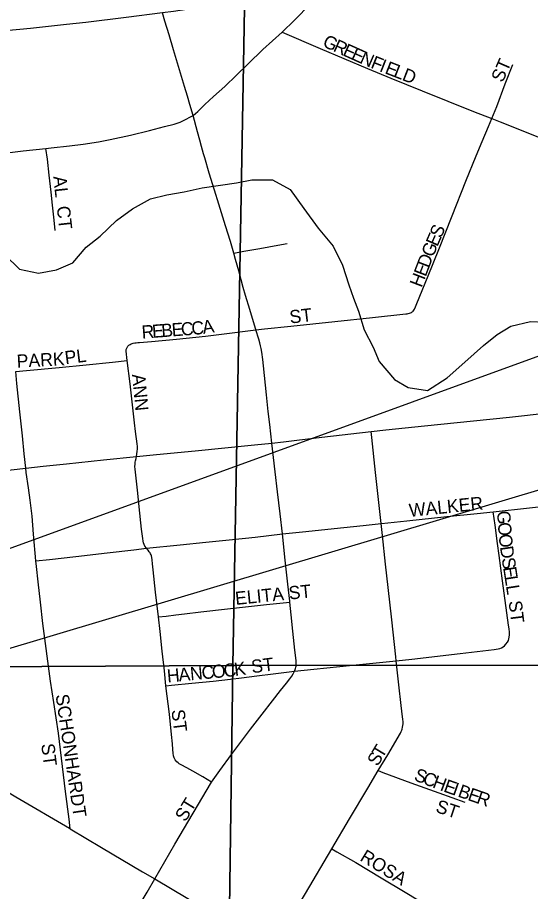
# Model space of a CAD drawing. Extents: x 0 to 34, y 0 to 22.
# Drawn here: x 5.9131 to 6.0976, y 18.3375 to 18.6521 of the extents above; entities that cross this region are included whole.
import ezdxf

# ---------------------------------------------------------------- set-up
doc = ezdxf.new("R2010")
doc.units = 0
for name, color, linetype in [('GM_X_City_Street', 7, 'Continuous'), ('GM_X_City_Street_Text', 7, 'Continuous'), ('GM_X_Minor_River', 7, 'Continuous'), ('GM_X_Section', 7, 'Continuous'), ('GM_X_State_Route', 7, 'Continuous'), ('SH_Text', 7, 'Continuous')]:
    doc.layers.add(name, color=color, linetype=linetype)

msp = doc.modelspace()

# ---------------------------------------------------------------- linework, layer by layer
at = {"layer": 'GM_X_City_Street'}
for points in [[(5.97623, 18.6169), (5.9751, 18.62082), (5.97423, 18.62383), (5.97321, 18.62735), (5.97211, 18.6309), (5.96925, 18.64045), (5.96763, 18.64587), (5.96614, 18.65085), (5.96526, 18.65378)], [(6.00829, 18.64679), (6.02199, 18.64096), (6.03895, 18.63373), (6.04742, 18.63029), (6.05863, 18.62578), (6.07711, 18.61832), (6.08371, 18.61573)], [(6.08371, 18.61573), (6.08545, 18.62011), (6.08855, 18.62823), (6.09128, 18.63517)], [(5.99093, 18.56728), (5.9897, 18.57147), (5.98794, 18.57712), (5.9855, 18.58494), (5.98398, 18.58994), (5.98207, 18.59612), (5.98044, 18.60161), (5.98002, 18.60302), (5.97931, 18.60566), (5.97867, 18.60798), (5.97785, 18.61094), (5.97623, 18.6169)], [(6.05443, 18.54579), (6.05479, 18.54599), (6.05506, 18.54618), (6.05523, 18.54633), (6.05538, 18.54648), (6.05565, 18.54682), (6.05583, 18.54713), (6.05598, 18.5474), (6.05676, 18.54914), (6.06078, 18.55918), (6.06462, 18.56867), (6.06944, 18.58076), (6.07437, 18.59316), (6.07811, 18.60236), (6.08025, 18.60752), (6.08249, 18.61284), (6.08371, 18.61573)], [(6.08371, 18.61573), (6.08668, 18.61457), (6.11581, 18.60294), (6.16051, 18.58493), (6.1907, 18.57271), (6.19139, 18.57243)], [(5.9267, 18.57545), (5.92632, 18.57923), (5.92572, 18.58463), (5.9252, 18.58929), (5.92452, 18.59537), (5.92387, 18.60115), (5.92335, 18.60502)], [(5.99093, 18.56728), (5.99457, 18.568), (6.00022, 18.56903), (6.00679, 18.57022), (6.01014, 18.57081)], [(5.99887, 18.53976), (5.99886, 18.5398), (5.99765, 18.54378), (5.99668, 18.54701), (5.99514, 18.55204), (5.99428, 18.555), (5.99267, 18.56099), (5.99157, 18.56507), (5.99093, 18.56728)], [(5.99887, 18.53976), (6.00193, 18.54012), (6.01144, 18.54108), (6.02726, 18.54266), (6.04076, 18.54413), (6.05279, 18.54541), (6.05326, 18.54546), (6.05366, 18.54553), (6.05409, 18.54566), (6.05443, 18.54579)], [(5.95284, 18.53383), (5.9532, 18.53418), (5.95363, 18.53444), (5.95403, 18.53465), (5.95439, 18.5348), (5.95474, 18.53491), (5.95527, 18.535), (5.95581, 18.53507), (5.9564, 18.53511), (5.95699, 18.53516), (5.96129, 18.53554), (5.97024, 18.53635), (5.98068, 18.5374), (5.98745, 18.53828), (5.99887, 18.53976)], [(6.00454, 18.49886), (6.00382, 18.50566), (6.0033, 18.51037), (6.0027, 18.51631), (6.00162, 18.5267), (6.0013, 18.52904), (6.00096, 18.53164), (6.00072, 18.53303), (6.00054, 18.534), (6.0003, 18.53498), (5.99992, 18.53633), (5.99887, 18.53976)], [(5.9526, 18.52869), (5.95217, 18.532), (5.95222, 18.53257), (5.95239, 18.53313), (5.95262, 18.53353), (5.95284, 18.53383)], [(5.91248, 18.52474), (5.91641, 18.52503), (5.92809, 18.52613), (5.93786, 18.52711), (5.94725, 18.52812), (5.9526, 18.52869)], [(5.95591, 18.49413), (5.95619, 18.49589), (5.95626, 18.49683), (5.95622, 18.4977), (5.95616, 18.49864), (5.95561, 18.50308), (5.95525, 18.50629), (5.95477, 18.51058), (5.95361, 18.52025), (5.9526, 18.52869)], [(5.91606, 18.48991), (5.91553, 18.49504), (5.91486, 18.50159), (5.91398, 18.51015), (5.91292, 18.52041), (5.91248, 18.52474)], [(6.04029, 18.50307), (6.04562, 18.50366), (6.05953, 18.5051), (6.07708, 18.50692), (6.09009, 18.50832), (6.11788, 18.51135), (6.13438, 18.51308), (6.14881, 18.51459), (6.15926, 18.51574), (6.16919, 18.51683), (6.19705, 18.51978)], [(6.00454, 18.49886), (6.00879, 18.49941), (6.0136, 18.50005), (6.02256, 18.5011), (6.04029, 18.50307)], [(6.04388, 18.46995), (6.04319, 18.47645), (6.04187, 18.48837), (6.04051, 18.50099), (6.04029, 18.50307)], [(5.95591, 18.49413), (5.96307, 18.49483), (5.97696, 18.49618), (5.99836, 18.49826), (6.00454, 18.49886)], [(6.00836, 18.46627), (6.00753, 18.47343), (6.00661, 18.48136), (6.00578, 18.48855), (6.00454, 18.49886)], [(5.91606, 18.48991), (5.92231, 18.49059), (5.93075, 18.4915), (5.94401, 18.49288), (5.95591, 18.49413)], [(5.95954, 18.4611), (5.95895, 18.46187), (5.95864, 18.46241), (5.95841, 18.46302), (5.95828, 18.46366), (5.95814, 18.46457), (5.95776, 18.46797), (5.95689, 18.47603), (5.95639, 18.48088), (5.95544, 18.48952), (5.95536, 18.49047), (5.95539, 18.49136), (5.95547, 18.49205), (5.95555, 18.4926), (5.95575, 18.49344), (5.95591, 18.49413)], [(5.87222, 18.48524), (5.87988, 18.48607), (5.89608, 18.48771), (5.90517, 18.48872), (5.91081, 18.48934), (5.91606, 18.48991)], [(5.91971, 18.45651), (5.91891, 18.46616), (5.91833, 18.47268), (5.91772, 18.47838), (5.91709, 18.48279), (5.91627, 18.48837), (5.91606, 18.48991)], [(6.08422, 18.47426), (6.0972, 18.47562), (6.10914, 18.47691), (6.12269, 18.47829), (6.1322, 18.47915), (6.13746, 18.47967)], [(6.04388, 18.46995), (6.04398, 18.46996), (6.05312, 18.47094), (6.06753, 18.47248), (6.07843, 18.47364), (6.08422, 18.47426)], [(6.08872, 18.42652), (6.08933, 18.42729), (6.08966, 18.4279), (6.08987, 18.42848), (6.08997, 18.42909), (6.09004, 18.42993), (6.09002, 18.43085), (6.08989, 18.43207), (6.08972, 18.4334), (6.08759, 18.44937), (6.0863, 18.45846), (6.08569, 18.46276), (6.08484, 18.46943), (6.08422, 18.47426)], [(6.00836, 18.46627), (6.01561, 18.46702), (6.03048, 18.46856), (6.03747, 18.46928), (6.04388, 18.46995)], [(6.04927, 18.42062), (6.04912, 18.42196), (6.04772, 18.43533), (6.0464, 18.44696), (6.0455, 18.45531), (6.04434, 18.46567), (6.04388, 18.46995)], [(5.95954, 18.4611), (5.97157, 18.46234), (5.9808, 18.46328), (5.99045, 18.46426), (5.99863, 18.46509), (6.00836, 18.46627)], [(6.01104, 18.44167), (6.011, 18.44205), (6.01034, 18.44819), (6.0094, 18.45685), (6.00836, 18.46627)], [(5.91971, 18.45651), (5.92467, 18.45708), (5.93409, 18.45816), (5.94541, 18.45947), (5.9549, 18.46057), (5.95954, 18.4611)], [(5.96386, 18.43637), (5.96323, 18.44132), (5.96272, 18.44531), (5.96188, 18.45338), (5.96166, 18.45547), (5.96152, 18.45694), (5.96141, 18.45772), (5.96127, 18.45835), (5.96113, 18.45875), (5.96098, 18.4591), (5.96079, 18.45942), (5.96052, 18.45982), (5.96008, 18.46041), (5.95954, 18.4611)], [(5.93206, 18.36014), (5.93164, 18.36357), (5.93043, 18.3735), (5.92786, 18.39454), (5.92616, 18.40553), (5.925, 18.41328), (5.92228, 18.43404), (5.92138, 18.44168), (5.92052, 18.44903), (5.91993, 18.45449), (5.91971, 18.45651)], [(5.96386, 18.43637), (5.96662, 18.4367), (5.97005, 18.43712), (5.97315, 18.4375), (5.97903, 18.43819), (5.98863, 18.43927), (5.99408, 18.43988), (6.00264, 18.44087), (6.01104, 18.44167)], [(6.01274, 18.4169), (6.01296, 18.41745), (6.01311, 18.41787), (6.01324, 18.41829), (6.0133, 18.4187), (6.01335, 18.41912), (6.01337, 18.41963), (6.01333, 18.4201), (6.01328, 18.42071), (6.01289, 18.4244), (6.01209, 18.4312), (6.01153, 18.4371), (6.01104, 18.44167)], [(5.9665, 18.41162), (5.96593, 18.41693), (5.96509, 18.42404), (5.96439, 18.43114), (5.96386, 18.43637)], [(6.04927, 18.42062), (6.05498, 18.4212), (6.07226, 18.42323), (6.08454, 18.42471), (6.08596, 18.4249), (6.08659, 18.42507), (6.0872, 18.42531), (6.08773, 18.42562), (6.08825, 18.42602), (6.08872, 18.42652)], [(6.01274, 18.4169), (6.01968, 18.41763), (6.03371, 18.41905), (6.04927, 18.42062)], [(6.04287, 18.38105), (6.04632, 18.38674), (6.05084, 18.39456), (6.05111, 18.39515), (6.0513, 18.39556), (6.05146, 18.39602), (6.05163, 18.39665), (6.05174, 18.39731), (6.05177, 18.39791), (6.05178, 18.39867), (6.05169, 18.39958), (6.05161, 18.4004), (6.05108, 18.40447), (6.05026, 18.41195), (6.04927, 18.42062)], [(5.9665, 18.41162), (5.96853, 18.41181), (5.97583, 18.41249), (5.9835, 18.41331), (5.98967, 18.41398), (5.99366, 18.41446), (5.99643, 18.41482), (5.9992, 18.41517), (6.00504, 18.41587), (6.01269, 18.4169), (6.01274, 18.4169)], [(5.98292, 18.37693), (5.98582, 18.38106), (5.99008, 18.38682), (5.99694, 18.39598), (6.00111, 18.40132), (6.00484, 18.40617), (6.00775, 18.40991), (6.00991, 18.41258), (6.0111, 18.41413), (6.0118, 18.4151), (6.01223, 18.41586), (6.01253, 18.41635), (6.01274, 18.4169)], [(5.98292, 18.37693), (5.97971, 18.37881), (5.97613, 18.38082), (5.97396, 18.38203), (5.97199, 18.38313), (5.97125, 18.38355), (5.97084, 18.38383), (5.97041, 18.38423), (5.96983, 18.38493), (5.96947, 18.38566), (5.96925, 18.38641), (5.96913, 18.38739), (5.96903, 18.38861), (5.96884, 18.39066), (5.96854, 18.39405), (5.96778, 18.40136), (5.9665, 18.41162)], [(5.88289, 18.3892), (5.89492, 18.38214), (5.91256, 18.37166), (5.93177, 18.36031), (5.93206, 18.36014)], [(6.0261, 18.35291), (6.03246, 18.36375), (6.03906, 18.37475), (6.04287, 18.38105)], [(6.04287, 18.38105), (6.04455, 18.38042), (6.05454, 18.37668), (6.06466, 18.37302), (6.07399, 18.36969)], [(5.96247, 18.34205), (5.96971, 18.35458), (5.98292, 18.37693)], [(5.93206, 18.36014), (5.94337, 18.35341), (5.95804, 18.34466), (5.96247, 18.34205)], [(6.00491, 18.31708), (6.0067, 18.32012), (6.01183, 18.32859), (6.01666, 18.33686), (6.0261, 18.35291)], [(6.0261, 18.35291), (6.02799, 18.35183), (6.03473, 18.34796), (6.04394, 18.34247), (6.05254, 18.33728), (6.06168, 18.33184)], [(5.92844, 18.30025), (5.93343, 18.30396), (5.93716, 18.30674), (5.9435, 18.31176), (5.94429, 18.31246), (5.94502, 18.31325), (5.94559, 18.31399), (5.94634, 18.31505), (5.94696, 18.31599), (5.95193, 18.32428), (5.9597, 18.33726), (5.96247, 18.34205)], [(5.96247, 18.34205), (5.97435, 18.33504), (5.98831, 18.32678), (6.00491, 18.31708)]]:
    msp.add_lwpolyline(points, dxfattribs=at)
at = {"layer": 'GM_X_Minor_River'}
msp.add_lwpolyline([(5.90861, 18.5667), (5.91388, 18.56154), (5.9207, 18.56016), (5.92716, 18.56125), (5.93306, 18.56386), (5.93785, 18.56952), (5.94281, 18.57346), (5.94873, 18.57911), (5.95445, 18.58324), (5.96093, 18.5868), (5.96682, 18.58827), (5.97309, 18.58936), (5.97955, 18.59083), (5.9919, 18.59264), (5.99741, 18.59373), (6.00481, 18.59368), (6.01123, 18.59021), (6.01612, 18.58335), (6.02119, 18.57629), (6.02664, 18.56979), (6.03001, 18.56294), (6.03223, 18.5559), (6.03391, 18.55115), (6.03577, 18.54639), (6.03781, 18.53973), (6.04099, 18.53344), (6.04323, 18.52831), (6.04868, 18.52181), (6.0536, 18.51893), (6.06061, 18.51793), (6.06766, 18.52243), (6.07396, 18.52807), (6.08065, 18.5341), (6.08561, 18.53804), (6.09057, 18.54104), (6.0976, 18.54269), (6.10272, 18.54247)], dxfattribs=at)
at = {"layer": 'GM_X_Section'}
msp.add_lwpolyline([(5.751, 18.66593), (5.77962, 18.69224), (5.79353, 18.70237), (5.81311, 18.71094), (5.83598, 18.72819), (5.85394, 18.74739), (5.86623, 18.76965), (5.88363, 18.79055), (5.90361, 18.82773), (5.91254, 18.85494), (5.91525, 18.86288), (5.91821, 18.87821), (5.92198, 18.90091), (5.93271, 18.91713), (5.93348, 18.91883), (5.93772, 18.9277), (5.9505, 18.93954), (5.96741, 18.95343), (5.99942, 18.91928), (5.99052, 18.41894), (5.46396, 18.4161)], dxfattribs=at)
for points in [[(6.51159, 18.92185), (6.50305, 18.41943), (5.99052, 18.41894), (5.99942, 18.91928)], [(6.50305, 18.41943), (6.4928, 17.91626), (5.98372, 17.92012), (5.99052, 18.41894)], [(5.99052, 18.41894), (5.98372, 17.92012), (5.4644, 17.92291), (5.46396, 18.4161)]]:
    msp.add_lwpolyline(points, close=True, dxfattribs=at)
at = {"layer": 'GM_X_State_Route'}
for points in [[(6.02332, 18.66153), (6.00702, 18.65953), (5.99331, 18.65785), (5.96918, 18.65426), (5.96526, 18.65378), (5.95225, 18.65218), (5.93766, 18.65038), (5.93079, 18.64956), (5.91779, 18.64821), (5.90874, 18.64727)], [(6.00829, 18.64679), (6.01268, 18.6512), (6.01846, 18.657), (6.02332, 18.66153)], [(5.91034, 18.60356), (5.91514, 18.6041), (5.92335, 18.60502), (5.92528, 18.60522), (5.93185, 18.60593), (5.93669, 18.60648), (5.94219, 18.60733), (5.94643, 18.60821), (5.95375, 18.60981), (5.96063, 18.61148), (5.96599, 18.61284), (5.96944, 18.61377), (5.97156, 18.61449), (5.97381, 18.61551), (5.97514, 18.61623), (5.97623, 18.6169), (5.97791, 18.61834), (5.97914, 18.61949), (5.98043, 18.62076), (5.98365, 18.62368), (5.98762, 18.62728), (5.9961, 18.63543), (6.0014, 18.64063), (6.00829, 18.64679)]]:
    msp.add_lwpolyline(points, dxfattribs=at)
at = {"layer": 'SH_Text'}
msp.add_lwpolyline([(9.91391, 19.62604), (5.3499, 18.25689), (9.91668, 19.92045)], close=True, dxfattribs=at)

# ---------------------------------------------------------------- texts
at = {"layer": 'GM_X_City_Street_Text'}
for s, height, rotation, p in [('G', 0.00473, 335.7912, (6.02252, 18.64186)), ('R', 0.00473, 335.7986, (6.02632, 18.64015)), ('E', 0.00473, 335.7934, (6.02974, 18.63861)), ('E', 0.00473, 335.7977, (6.03279, 18.63724)), ('N', 0.00473, 336.4504, (6.03588, 18.63585)), ('F', 0.00473, 338.3393, (6.03986, 18.63412)), ('I', 0.00473, 338.6686, (6.04298, 18.63288)), ('ST', 0.004735, 66.3692, (6.08759, 18.62849)), ('E', 0.00473, 338.6809, (6.04492, 18.63212)), ('L', 0.00473, 338.6604, (6.04803, 18.63091)), ('D', 0.00473, 338.6733, (6.05113, 18.6297)), ('AL', 0.004735, 276.0066, (5.92596, 18.59489)), ('CT', 0.004735, 276.3362, (5.92721, 18.58406)), ('S', 0.00473, 66.0625, (6.06542, 18.57246)), ('E', 0.00473, 66.4786, (6.0641, 18.56941)), ('G', 0.00473, 68.3285, (6.06257, 18.56558)), ('D', 0.00473, 69.058, (6.06109, 18.5617)), ('E', 0.00473, 69.0507, (6.0599, 18.55859)), ('H', 0.00473, 69.0551, (6.05841, 18.5547)), ('ST', 0.004735, 6.7054, (6.01122, 18.54193)), ('B', 0.00473, 4.2697, (5.96499, 18.53705)), ('E', 0.00473, 4.2685, (5.96873, 18.53733)), ('C', 0.00473, 4.2697, (5.97205, 18.53757)), ('C', 0.00473, 4.7689, (5.97584, 18.53786)), ('A', 0.00473, 8.8555, (5.97994, 18.53821)), ('R', 0.00473, 4.2777, (5.95793, 18.53652)), ('E', 0.00473, 4.2667, (5.96167, 18.5368)), ('PL', 0.004735, 7.1217, (5.93039, 18.52729)), ('PARK', 0.004735, 3.1778, (5.91294, 18.52604)), ('ANN', 0.004735, 275.5312, (5.95429, 18.52363)), ('WALKER', 0.004735, 5.8034, (6.05415, 18.47235)), ('G', 0.00473, 274.1339, (6.08555, 18.47444)), ('O', 0.00473, 274.1576, (6.08585, 18.47028)), ('O', 0.00473, 275.4704, (6.08616, 18.46601)), ('D', 0.00473, 278.5243, (6.08659, 18.46159)), ('S', 0.00473, 278.8276, (6.08721, 18.45744)), ('E', 0.00473, 278.841, (6.08772, 18.45415)), ('L', 0.00473, 278.8334, (6.08824, 18.45085)), ('ELITA ST', 0.004735, 5.7131, (5.99162, 18.44068)), ('L', 0.00473, 278.841, (6.08875, 18.44756)), ('ST', 0.004735, 277.1351, (6.08971, 18.44199)), ('O', 0.00473, 5.2973, (5.98326, 18.41427)), ('C', 0.00473, 6.2933, (5.9875, 18.41466)), ('K', 0.00473, 7.5526, (5.99134, 18.41509)), ('ST', 0.004735, 7.1217, (5.99747, 18.4161)), ('H', 0.00473, 5.2973, (5.96708, 18.41277)), ('A', 0.00473, 5.3237, (5.97123, 18.41315)), ('N', 0.00473, 5.2973, (5.97538, 18.41354)), ('C', 0.00473, 5.3281, (5.97953, 18.41392)), ('SCHONHARDT', 0.004735, 278.3827, (5.92679, 18.40827)), ('ST', 0.004735, 277.1351, (5.96846, 18.40282)), ('ST', 0.004735, 277.1217, (5.92163, 18.39056)), ('T', 0.00473, 58.8113, (6.04432, 18.38519)), ('S', 0.00473, 59.5705, (6.04264, 18.38233)), ('S', 0.00473, 338.6604, (6.0554, 18.37771)), ('C', 0.00473, 338.654, (6.0585, 18.3765)), ('H', 0.00473, 339.2715, (6.06205, 18.37511)), ('E', 0.00473, 340.5065, (6.06605, 18.3736)), ('I', 0.00473, 340.7201, (6.06921, 18.37248)), ('B', 0.00473, 340.6974, (6.07118, 18.37179)), ('E', 0.00473, 340.7302, (6.07472, 18.37055)), ('R', 0.00473, 340.7203, (6.07787, 18.36945)), ('ST', 0.004735, 58.3953, (5.97348, 18.36235)), ('ST', 0.004735, 341.5607, (6.0632, 18.36625)), ('ROSA', 0.004735, 328.4929, (6.03596, 18.34889))]:
    msp.add_text(s, height=height, rotation=rotation, dxfattribs=at).set_placement(p)

doc.saveas('drawing.dxf')
